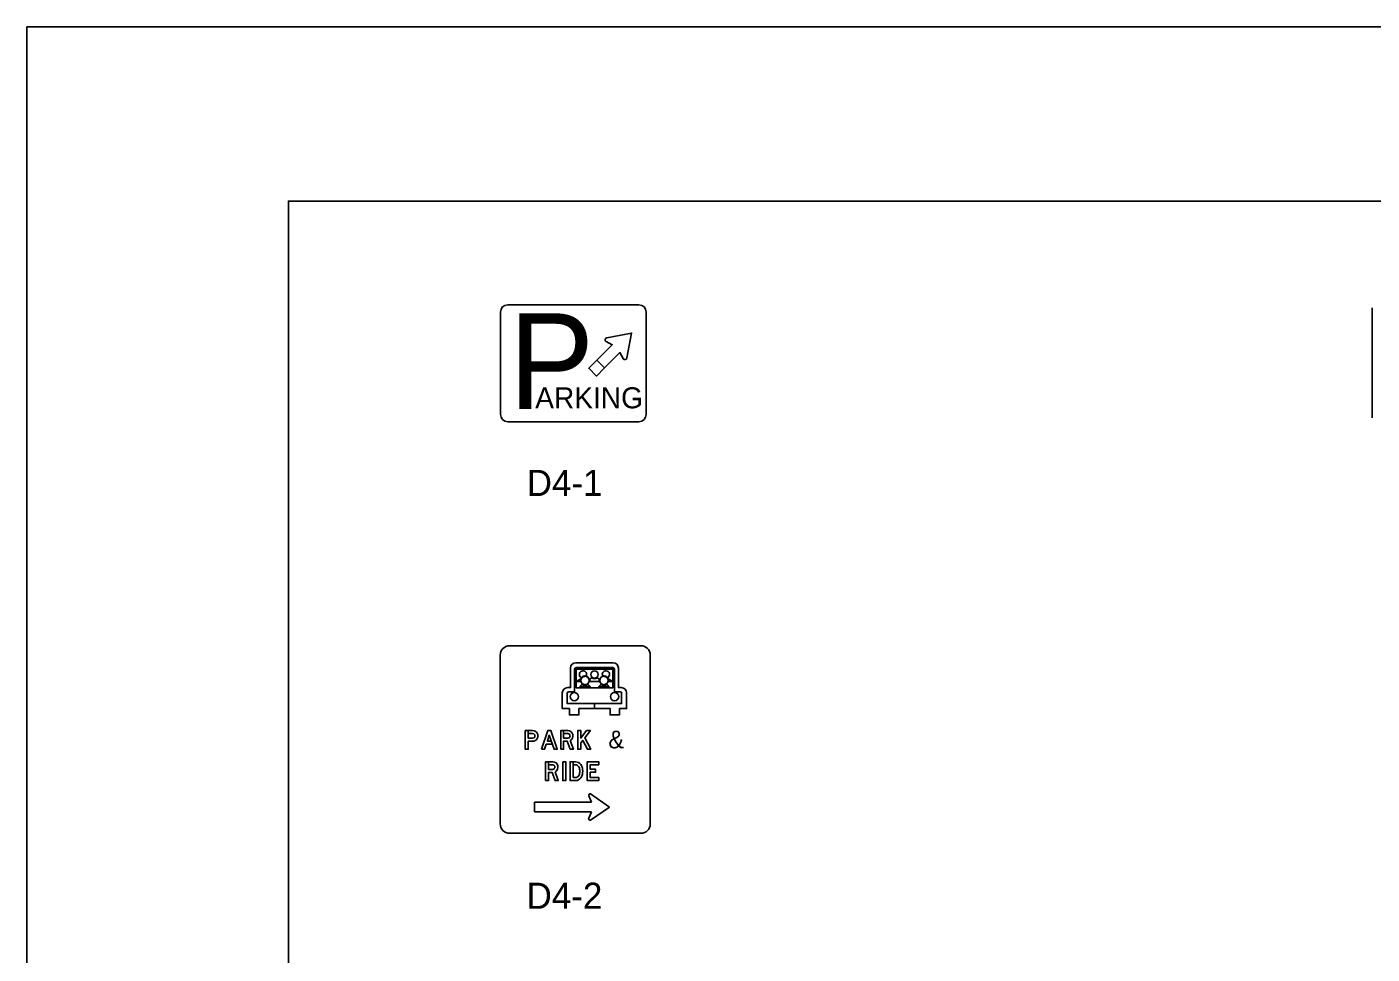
# Model space of a CAD drawing. Extents: x 42133 to 45533, y 41351 to 47951.
# Drawn here: x 42133.3 to 42519.1, y 47685.3 to 47951.4 of the extents above; entities that cross this region are included whole.
import ezdxf

# ---------------------------------------------------------------- set-up
doc = ezdxf.new("R2010")
doc.units = 0
for name, color, linetype in [('#plot_shape', 7, 'Continuous'), ('P_ODOT_PLAN_Border', 7, 'Continuous'), ('P_TRAF_SIGN_SignDetails', 7, 'Continuous')]:
    doc.layers.add(name, color=color, linetype=linetype)

msp = doc.modelspace()

# ---------------------------------------------------------------- linework, layer by layer
at = {"layer": '#plot_shape'}
msp.add_lwpolyline([(42133.34, 46851.35), (43833.34, 46851.35), (43833.34, 47951.35), (42133.34, 47951.35)], close=True, dxfattribs=at)
at = {"layer": 'P_ODOT_PLAN_Border'}
msp.add_lwpolyline([(42208.34, 46901.35), (43808.34, 46901.35), (43808.34, 47901.35), (42208.34, 47901.35)], close=True, dxfattribs=at)
at = {"layer": 'P_TRAF_SIGN_SignDetails'}
for p, q in [((42269.14, 47840.15), (42269.14, 47869.53)), ((42271.24, 47871.63), (42308.85, 47871.63)), ((42310.94, 47869.53), (42310.94, 47840.15)), ((42519.13, 47839.2), (42519.13, 47870.7)), ((42308.85, 47838.06), (42271.24, 47838.06)), ((42309.44, 47773.77), (42271.78, 47773.77)), ((42269.09, 47771.08), (42269.09, 47722.65)), ((42312.13, 47722.65), (42312.13, 47771.08)), ((42290.69, 47735.96), (42289.99, 47735.96)), ((42294.48, 47730.67), (42295.24, 47728.87)), ((42300.47, 47727.5), (42295.02, 47731.25)), ((42295.24, 47728.87), (42278.96, 47728.87)), ((42278.96, 47728.87), (42278.96, 47726.14)), ((42295.02, 47723.75), (42300.47, 47727.5)), ((42278.96, 47726.14), (42295.23, 47726.14)), ((42295.23, 47726.14), (42294.47, 47724.34)), ((42295, 47723.75), (42295.02, 47723.75)), ((42295, 47723.75), (42295, 47723.75)), ((42271.78, 47719.96), (42309.44, 47719.96))]:
    msp.add_line(p, q, dxfattribs=at)
for points in [[(42305.44, 47856.38), (42306.77, 47863.5), (42299.65, 47862.17)], [(42305.44, 47856.38), (42306.77, 47863.5), (42299.65, 47862.17)], [(42305.44, 47856.38), (42306.77, 47863.5), (42299.65, 47862.17)], [(42299.48, 47861.04), (42301.19, 47860.13), (42296.76, 47855.69)], [(42299.48, 47861.04), (42301.19, 47860.13), (42296.76, 47855.69)], [(42299.48, 47861.04), (42301.19, 47860.13), (42296.76, 47855.69)], [(42296.76, 47855.69), (42298.96, 47853.49), (42303.4, 47857.92), (42304.31, 47856.21)], [(42296.76, 47855.69), (42298.96, 47853.49), (42303.4, 47857.92), (42304.31, 47856.21)], [(42296.76, 47855.69), (42298.96, 47853.49), (42303.4, 47857.92), (42304.31, 47856.21)], [(42288.43, 47761.75), (42289.25, 47761.75), (42289.25, 47767.38)], [(42289.25, 47767.38), (42289.25, 47761.75), (42288.43, 47761.75)], [(42289.25, 47767.38), (42289.25, 47761.75), (42288.43, 47761.75)], [(42288.73, 47760.59), (42290.41, 47760.59), (42290.41, 47767.08)], [(42288.73, 47760.59), (42290.41, 47760.59), (42290.41, 47767.08)], [(42288.73, 47760.59), (42290.41, 47760.59), (42290.41, 47767.08)], [(42290.79, 47768.92), (42301.44, 47768.92)], [(42301.44, 47768.92), (42290.79, 47768.92)], [(42301.44, 47768.92), (42290.79, 47768.92)], [(42290.83, 47767.49), (42301.4, 47767.49)], [(42290.83, 47767.49), (42301.4, 47767.49)], [(42290.83, 47767.49), (42301.4, 47767.49)], [(42290.83, 47761.72), (42290.83, 47767)], [(42301.4, 47767), (42301.4, 47761.72), (42290.83, 47761.72)], [(42292.17, 47764.33), (42290.88, 47763.55), (42290.83, 47763.55), (42290.83, 47767)], [(42301.4, 47767), (42301.4, 47761.72), (42290.83, 47761.72), (42290.83, 47763.55), (42292.09, 47763.55)], [(42292.17, 47764.33), (42290.88, 47763.55), (42290.83, 47763.55), (42290.83, 47767)], [(42301.4, 47767), (42301.4, 47761.72), (42290.83, 47761.72), (42290.83, 47763.55), (42292.09, 47763.55)], [(42290.9, 47767.08), (42301.33, 47767.08)], [(42290.9, 47767.08), (42301.33, 47767.08)], [(42290.9, 47767.08), (42301.33, 47767.08)], [(42301.81, 47767.08), (42301.81, 47760.59), (42303.5, 47760.59)], [(42301.81, 47767.08), (42301.81, 47760.59), (42303.5, 47760.59)], [(42301.81, 47767.08), (42301.81, 47760.59), (42303.5, 47760.59)], [(42302.98, 47767.38), (42302.98, 47761.75), (42303.8, 47761.75)], [(42303.8, 47761.75), (42302.98, 47761.75), (42302.98, 47767.38)], [(42303.8, 47761.75), (42302.98, 47761.75), (42302.98, 47767.38)], [(42292.09, 47763.55), (42290.88, 47763.55), (42292.17, 47764.33)], [(42291.92, 47762.05), (42292.61, 47762.73)], [(42294.21, 47762.73), (42294.9, 47762.05), (42291.92, 47762.05)], [(42292.61, 47762.73), (42291.92, 47762.05), (42294.9, 47762.05), (42294.21, 47762.73)], [(42292.61, 47762.73), (42291.92, 47762.05), (42294.9, 47762.05), (42294.21, 47762.73)], [(42292.22, 47763.93), (42292.07, 47763.95)], [(42292.07, 47763.95), (42292.22, 47763.93)], [(42292.22, 47763.93), (42292.07, 47763.95)], [(42292.07, 47763.95), (42292.22, 47763.93)], [(42293.03, 47764.95), (42292.98, 47765.09)], [(42292.98, 47765.09), (42293.03, 47764.95)], [(42293.03, 47764.95), (42292.98, 47765.09)], [(42292.98, 47765.09), (42293.03, 47764.95)], [(42293.41, 47762.61), (42293.41, 47762.46)], [(42293.41, 47762.46), (42293.41, 47762.61)], [(42293.41, 47762.61), (42293.41, 47762.46)], [(42293.41, 47762.46), (42293.41, 47762.61)], [(42294.76, 47763.86), (42294.61, 47763.85)], [(42294.61, 47763.85), (42294.76, 47763.86)], [(42294.76, 47763.86), (42294.61, 47763.85)], [(42294.61, 47763.85), (42294.76, 47763.86)], [(42295.37, 47764.58), (42294.72, 47764.16)], [(42295.37, 47764.58), (42294.72, 47764.16)], [(42295.37, 47764.58), (42294.72, 47764.16)], [(42294.74, 47763.55), (42297.49, 47763.55)], [(42294.74, 47763.55), (42297.49, 47763.55)], [(42294.74, 47763.55), (42297.49, 47763.55)], [(42296.11, 47764.33), (42296.11, 47764.49)], [(42296.11, 47764.49), (42296.11, 47764.33)], [(42296.11, 47764.33), (42296.11, 47764.49)], [(42296.11, 47764.49), (42296.11, 47764.33)], [(42297.51, 47764.16), (42296.86, 47764.58)], [(42297.51, 47764.16), (42296.86, 47764.58)], [(42297.51, 47764.16), (42296.86, 47764.58)], [(42297.33, 47762.05), (42298.01, 47762.73)], [(42299.62, 47762.73), (42300.3, 47762.05), (42297.33, 47762.05)], [(42298.01, 47762.73), (42297.33, 47762.05), (42300.3, 47762.05), (42299.62, 47762.73)], [(42298.01, 47762.73), (42297.33, 47762.05), (42300.3, 47762.05), (42299.62, 47762.73)], [(42297.62, 47763.85), (42297.47, 47763.86)], [(42297.47, 47763.86), (42297.62, 47763.85)], [(42297.62, 47763.85), (42297.47, 47763.86)], [(42297.47, 47763.86), (42297.62, 47763.85)], [(42298.81, 47762.61), (42298.81, 47762.46)], [(42298.81, 47762.46), (42298.81, 47762.61)], [(42298.81, 47762.61), (42298.81, 47762.46)], [(42298.81, 47762.46), (42298.81, 47762.61)], [(42299.2, 47764.95), (42299.25, 47765.09)], [(42299.25, 47765.09), (42299.2, 47764.95)], [(42299.2, 47764.95), (42299.25, 47765.09)], [(42299.25, 47765.09), (42299.2, 47764.95)], [(42300.16, 47763.95), (42300.01, 47763.93)], [(42300.01, 47763.93), (42300.16, 47763.95)], [(42300.16, 47763.95), (42300.01, 47763.93)], [(42300.01, 47763.93), (42300.16, 47763.95)], [(42301.35, 47763.55), (42300.06, 47764.33)], [(42300.14, 47763.55), (42301.35, 47763.55), (42300.06, 47764.33)], [(42300.14, 47763.55), (42301.35, 47763.55), (42300.06, 47764.33)], [(42300.14, 47763.55), (42301.35, 47763.55)], [(42300.58, 47753.92), (42300.58, 47755.74), (42291.65, 47755.74), (42291.65, 47753.92), (42288.95, 47753.92), (42288.95, 47755.74), (42286.89, 47755.74), (42286.89, 47760.22)], [(42286.89, 47760.22), (42286.89, 47755.74)], [(42286.89, 47760.22), (42286.89, 47755.74)], [(42286.89, 47755.74), (42288.95, 47755.74), (42288.95, 47753.92), (42291.65, 47753.92), (42291.65, 47755.74), (42296.11, 47755.74), (42296.11, 47757.18), (42288.31, 47757.18), (42288.31, 47760.18)], [(42286.89, 47755.74), (42288.95, 47755.74), (42288.95, 47753.92), (42291.65, 47753.92), (42291.65, 47755.74), (42296.11, 47755.74), (42296.11, 47757.18), (42288.31, 47757.18), (42288.31, 47760.18)], [(42288.31, 47757.18), (42288.31, 47760.18)], [(42303.91, 47760.18), (42303.91, 47757.18), (42288.31, 47757.18)], [(42303.91, 47760.18), (42303.91, 47757.18), (42296.11, 47757.18), (42296.11, 47755.74), (42300.58, 47755.74), (42300.58, 47753.92), (42303.28, 47753.92), (42303.28, 47755.74), (42305.34, 47755.74), (42305.34, 47760.22)], [(42303.91, 47760.18), (42303.91, 47757.18), (42296.11, 47757.18), (42296.11, 47755.74), (42300.58, 47755.74), (42300.58, 47753.92), (42303.28, 47753.92), (42303.28, 47755.74), (42305.34, 47755.74), (42305.34, 47760.22)], [(42305.34, 47760.22), (42305.34, 47755.74), (42303.28, 47755.74), (42303.28, 47753.92), (42300.58, 47753.92)], [(42277.12, 47749.44), (42276.28, 47749.44), (42276.28, 47744.06), (42277.12, 47744.06), (42277.12, 47746.36), (42278.38, 47746.36)], [(42278.38, 47747.22), (42277.12, 47747.22), (42277.12, 47749.44)], [(42278.38, 47749.44), (42277.13, 47749.44), (42277.13, 47748.58), (42278.38, 47748.58)], [(42288.5, 47747.27), (42287.27, 47747.27), (42287.27, 47749.44), (42286.42, 47749.44), (42286.42, 47744.06)], [(42286.42, 47744.06), (42287.27, 47744.06), (42287.27, 47746.41), (42288.26, 47746.41), (42289.15, 47744.06), (42290.06, 47744.06), (42289.14, 47746.6)], [(42288.5, 47749.44), (42287.27, 47749.44), (42287.27, 47748.58), (42288.5, 47748.58)], [(42284.18, 47738.3), (42282.96, 47738.3), (42282.96, 47740.47), (42282.11, 47740.47), (42282.11, 47735.09)], [(42284.18, 47740.47), (42282.96, 47740.47), (42282.96, 47739.61), (42284.18, 47739.61)], [(42289.99, 47735.96), (42289.99, 47740.48), (42289.14, 47740.48), (42289.14, 47735.1), (42290.69, 47735.1)], [(42290.69, 47740.48), (42289.99, 47740.48), (42289.99, 47739.62), (42290.69, 47739.62)], [(42282.11, 47735.09), (42282.96, 47735.09), (42282.96, 47737.45), (42283.94, 47737.45), (42284.83, 47735.09), (42285.74, 47735.09), (42284.81, 47737.64)]]:
    msp.add_lwpolyline(points, dxfattribs=at)
for points in [[(42296.76, 47855.69), (42294.45, 47853.39), (42296.67, 47851.17), (42298.98, 47853.48)], [(42280.91, 47744.06), (42282.71, 47749.44), (42283.61, 47749.44), (42285.42, 47744.06), (42284.52, 47744.06), (42283.16, 47748.11), (42282.6, 47746.4), (42283.74, 47746.4), (42284.02, 47745.53), (42282.3, 47745.53), (42281.8, 47744.06)], [(42292.17, 47744.06), (42292.17, 47745.88), (42292.75, 47746.62), (42294.08, 47744.06), (42295.04, 47744.06), (42293.32, 47747.36), (42294.93, 47749.44), (42293.85, 47749.44), (42292.17, 47747.27), (42292.17, 47749.44), (42291.32, 47749.44), (42291.32, 47744.06)], [(42287.01, 47740.47), (42287.86, 47740.47), (42287.86, 47735.09), (42287.01, 47735.09)], [(42297.32, 47739.61), (42294.89, 47739.61), (42294.89, 47738.32), (42296.42, 47738.32), (42296.42, 47737.46), (42294.89, 47737.46), (42294.89, 47735.95), (42297.32, 47735.95), (42297.32, 47735.09), (42294.04, 47735.09), (42294.04, 47740.47), (42297.32, 47740.47)]]:
    msp.add_lwpolyline(points, close=True, dxfattribs=at)
for centre, radius, start, end in [((42271.24, 47869.53), 2.09, 90, 180), ((42308.85, 47869.53), 2.09, 0, 90), ((42299.76, 47861.57), 0.606, 100.6003, 242.0573), ((42299.76, 47861.57), 0.606, 100.6003, 242.0573), ((42299.76, 47861.57), 0.606, 100.6003, 242.0573), ((42304.84, 47856.49), 0.606, 207.9427, 349.3997), ((42304.84, 47856.49), 0.606, 207.9427, 349.3997), ((42304.84, 47856.49), 0.606, 207.9427, 349.3997), ((42271.24, 47840.15), 2.09, 180, 270), ((42308.85, 47840.15), 2.09, 270, 360), ((42271.78, 47771.08), 2.69, 90, 180), ((42309.44, 47771.08), 2.69, 0, 90), ((42290.79, 47767.38), 1.54, 90, 180), ((42290.79, 47767.38), 1.54, 90, 180), ((42290.79, 47767.38), 1.54, 90, 180), ((42290.83, 47767.08), 0.413, 90, 180), ((42290.83, 47767.08), 0.413, 90, 180), ((42290.83, 47767.08), 0.413, 90, 180), ((42290.9, 47767), 0.075, 90, 180), ((42290.9, 47767), 0.075, 90, 180), ((42290.9, 47767), 0.075, 90, 180), ((42292.82, 47765.54), 1.05, 90, 242.057), ((42292.82, 47765.54), 1.05, 90, 242.057), ((42292.82, 47765.54), 1.05, 90, 242.057), ((42293.41, 47763.81), 1.35, 74.3062, 143.3444), ((42292.82, 47765.54), 1.05, 335.5937, 90), ((42292.82, 47765.54), 1.05, 335.5937, 90), ((42292.82, 47765.54), 1.05, 335.5937, 90), ((42293.41, 47763.81), 1.35, 74.3062, 108.7935), ((42293.41, 47763.81), 1.35, 74.3062, 108.7935), ((42296.11, 47765.54), 1.05, 90, 270), ((42296.11, 47765.54), 1.05, 90, 270), ((42296.11, 47765.54), 1.05, 90, 270), ((42296.11, 47765.54), 1.05, 270, 90), ((42296.11, 47765.54), 1.05, 270.0409, 90), ((42296.11, 47765.54), 1.05, 270.0409, 90), ((42299.41, 47765.54), 1.05, 90, 204.4063), ((42299.41, 47765.54), 1.05, 90, 204.4063), ((42299.41, 47765.54), 1.05, 90, 204.4063), ((42298.81, 47763.81), 1.35, 36.6556, 105.6938), ((42298.81, 47763.81), 1.35, 71.2065, 105.6938), ((42298.81, 47763.81), 1.35, 71.2065, 105.6938), ((42299.41, 47765.54), 1.05, 297.943, 90), ((42299.41, 47765.54), 1.05, 297.943, 90), ((42299.41, 47765.54), 1.05, 297.943, 90), ((42301.33, 47767), 0.075, 0, 90), ((42301.33, 47767), 0.075, 0, 90), ((42301.33, 47767), 0.075, 0, 90), ((42301.4, 47767.08), 0.413, 0, 90), ((42301.4, 47767.08), 0.413, 0, 90), ((42301.4, 47767.08), 0.413, 0, 90), ((42301.44, 47767.38), 1.54, 0, 90), ((42301.44, 47767.38), 1.54, 0, 90), ((42301.44, 47767.38), 1.54, 0, 90), ((42288.43, 47760.22), 1.54, 90, 180), ((42288.43, 47760.22), 1.54, 90, 180), ((42288.43, 47760.22), 1.54, 90, 180), ((42293.41, 47763.81), 1.35, 157.2515, 191.0322), ((42293.41, 47763.81), 1.35, 174.1418, 191.0322), ((42293.41, 47763.81), 1.35, 174.1418, 191.0322), ((42293.41, 47763.81), 1.35, 157.2515, 174.11), ((42293.41, 47763.81), 1.35, 157.2515, 174.11), ((42293.41, 47763.81), 1.2, 90, 270), ((42293.41, 47763.81), 1.2, 174.1418, 270), ((42293.41, 47763.81), 1.2, 174.1418, 270), ((42293.41, 47763.81), 1.2, 108.8253, 174.106), ((42293.41, 47763.81), 1.2, 108.8253, 174.106), ((42293.41, 47763.81), 1.35, 108.8253, 143.3444), ((42293.41, 47763.81), 1.35, 108.8253, 143.3444), ((42293.41, 47763.81), 1.35, 233.5463, 306.4537), ((42293.41, 47763.81), 1.35, 233.5463, 270), ((42293.41, 47763.81), 1.35, 233.5463, 270), ((42293.41, 47763.81), 1.2, 90, 108.7895), ((42293.41, 47763.81), 1.2, 90, 108.7895), ((42293.41, 47763.81), 1.2, 270, 90), ((42293.41, 47763.81), 1.2, 2.0184, 90), ((42293.41, 47763.81), 1.2, 2.0184, 90), ((42293.41, 47763.81), 1.2, 270.0358, 1.9825), ((42293.41, 47763.81), 1.2, 270.0358, 1.9825), ((42293.41, 47763.81), 1.35, 270.0318, 306.4537), ((42293.41, 47763.81), 1.35, 270.0318, 306.4537), ((42293.41, 47763.81), 1.35, 348.9678, 14.9973), ((42293.41, 47763.81), 1.35, 2.0144, 14.9973), ((42293.41, 47763.81), 1.35, 2.0144, 14.9973), ((42293.41, 47763.81), 1.35, 348.9678, 1.9825), ((42293.41, 47763.81), 1.35, 348.9678, 1.9825), ((42296.11, 47765.54), 1.22, 232.2604, 307.7396), ((42296.11, 47765.54), 1.22, 232.2604, 270), ((42296.11, 47765.54), 1.22, 232.2604, 270), ((42296.11, 47765.54), 1.22, 270.0354, 307.7396), ((42296.11, 47765.54), 1.22, 270.0354, 307.7396), ((42298.81, 47763.81), 1.35, 165.0027, 191.0322), ((42298.81, 47763.81), 1.35, 178.0175, 191.0322), ((42298.81, 47763.81), 1.35, 178.0175, 191.0322), ((42298.81, 47763.81), 1.35, 165.0027, 177.9856), ((42298.81, 47763.81), 1.35, 165.0027, 177.9856), ((42298.81, 47763.81), 1.2, 90, 270), ((42298.81, 47763.81), 1.2, 178.0175, 269.9642), ((42298.81, 47763.81), 1.2, 178.0175, 269.9642), ((42298.81, 47763.81), 1.2, 90, 177.9816), ((42298.81, 47763.81), 1.2, 90, 177.9816), ((42298.81, 47763.81), 1.35, 233.5463, 306.4537), ((42298.81, 47763.81), 1.35, 233.5463, 269.9682), ((42298.81, 47763.81), 1.35, 233.5463, 269.9682), ((42298.81, 47763.81), 1.2, 270, 90), ((42298.81, 47763.81), 1.2, 71.2105, 90), ((42298.81, 47763.81), 1.2, 71.2105, 90), ((42298.81, 47763.81), 1.2, 270, 5.8582), ((42298.81, 47763.81), 1.2, 270, 5.8582), ((42298.81, 47763.81), 1.35, 270, 306.4537), ((42298.81, 47763.81), 1.35, 270, 306.4537), ((42298.81, 47763.81), 1.2, 5.894, 71.1747), ((42298.81, 47763.81), 1.2, 5.894, 71.1747), ((42298.81, 47763.81), 1.35, 36.6556, 71.1747), ((42298.81, 47763.81), 1.35, 36.6556, 71.1747), ((42298.81, 47763.81), 1.35, 348.9678, 22.7485), ((42298.81, 47763.81), 1.35, 5.89, 22.7485), ((42298.81, 47763.81), 1.35, 5.89, 22.7485), ((42298.81, 47763.81), 1.35, 348.9678, 5.8582), ((42298.81, 47763.81), 1.35, 348.9678, 5.8582), ((42303.8, 47760.22), 1.54, 0, 90), ((42303.8, 47760.22), 1.54, 0, 90), ((42303.8, 47760.22), 1.54, 0, 90), ((42288.73, 47760.18), 0.413, 90, 180), ((42288.73, 47760.18), 0.413, 90, 180), ((42288.73, 47760.18), 0.413, 90, 180), ((42290.34, 47759.17), 1.2, 90, 270), ((42290.34, 47759.17), 1.2, 90, 270), ((42290.34, 47759.17), 1.2, 90, 270), ((42290.34, 47759.17), 1.2, 270, 90), ((42290.34, 47759.17), 1.2, 270, 90), ((42290.34, 47759.17), 1.2, 270, 90), ((42301.89, 47759.17), 1.2, 90, 270), ((42301.89, 47759.17), 1.2, 90, 270), ((42301.89, 47759.17), 1.2, 90, 270), ((42301.89, 47759.17), 1.2, 270, 90), ((42301.89, 47759.17), 1.2, 270, 90), ((42301.89, 47759.17), 1.2, 270, 90), ((42303.5, 47760.18), 0.413, 0, 90), ((42303.5, 47760.18), 0.413, 0, 90), ((42303.5, 47760.18), 0.413, 0, 90), ((42271.78, 47722.65), 2.69, 180, 270), ((42309.44, 47722.65), 2.69, 270, 0)]:
    msp.add_arc(centre, radius, start, end, dxfattribs=at)
for centre, major_axis, ratio, start_param, end_param in [((42278.4, 47747.9), (0, -1.54), 0.985, 6.270631, 9.437332), ((42278.39, 47747.9), (0, 0.676), 0.985, 3.119245, 6.305533), ((42288.47, 47747.94), (0, -1.5), 0.985, 0.466811, 3.12325), ((42288.45, 47747.92), (0, 0.655), 0.985, 3.211299, 6.213479), ((42284.15, 47738.97), (0, -1.5), 0.985, 0.466811, 3.12325), ((42284.13, 47738.96), (0, 0.655), 0.985, 3.211299, 6.213479), ((42290.72, 47738.62), (0, 1.85), 0.985, 5.308839, 6.296321), ((42290.68, 47738.51), (0, 1.1), 0.985, 5.20995, 6.265163), ((42290.04, 47738.15), (0, 1.85), 0.985, 4.827175, 5.217261), ((42287.88, 47737.88), (0, 4.06), 0.985, 4.688182, 4.829308), ((42290.36, 47738.25), (0, 2.37), 0.985, 4.893786, 5.353219), ((42286.77, 47737.74), (0, 6.05), 0.985, 4.719398, 4.866955), ((42290.68, 47737.06), (0, -1.1), 0.985, 0.018002, 1.073215), ((42290.72, 47736.95), (0, -1.85), 0.985, 6.270036, 7.257518), ((42290.04, 47737.43), (0, -1.85), 0.985, 1.065936, 1.456022), ((42287.88, 47737.69), (0, 4.06), 0.985, 4.59547, 4.736596), ((42290.36, 47737.33), (0, -2.37), 0.985, 0.929966, 1.389399), ((42286.77, 47737.83), (0, -6.05), 0.985, 1.416232, 1.563789), ((42294.83, 47730.86), (0, -0.45), 0.846872, 2.614965, 5.174213), ((42294.82, 47724.14), (0, 0.45), 0.846872, 1.114419, 3.66822)]:
    msp.add_ellipse(centre, major_axis=major_axis, ratio=ratio, start_param=start_param, end_param=end_param, dxfattribs=at)

# ---------------------------------------------------------------- texts
for s, height, p in [('P', 27.4, (42271.55, 47841.75)), ('ARKING', 6.028, (42279.12, 47841.91)), ('D4-1', 7.5, (42276.68, 47816.75)), ('&', 5.08, (42300.08, 47744.33)), ('D4-2', 7.5, (42276.64, 47698.29))]:
    msp.add_text(s, height=height, dxfattribs=at).set_placement(p)

doc.saveas('drawing.dxf')
